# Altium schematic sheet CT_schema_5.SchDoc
size 251 x 159 mm
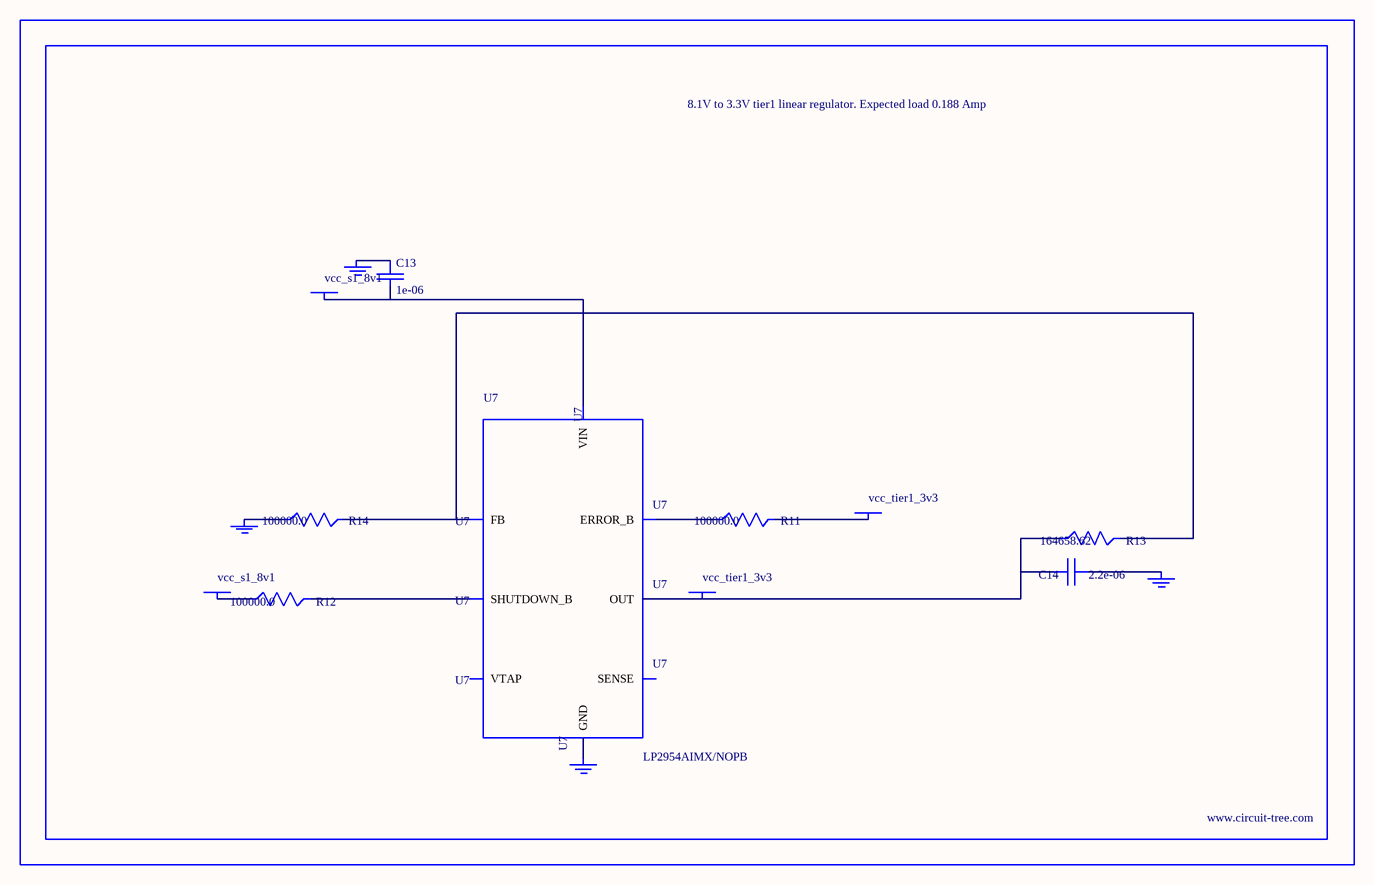
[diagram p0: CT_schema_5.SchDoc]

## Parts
BORDER4  (no value)
C13  1e-06  [EXV-9B]
C14  2.2e-06  [EXV-9B]
GND_INSTANCE_4_0  (no value)
GND_INSTANCE_4_1  (no value)
GND_INSTANCE_4_2  (no value)
GND_INSTANCE_4_3  (no value)
POWER_INSTANCE_4_0  vcc_s1_8v1
POWER_INSTANCE_4_1  vcc_tier1_3v3
POWER_INSTANCE_4_2  vcc_s1_8v1
POWER_INSTANCE_4_3  vcc_tier1_3v3
R11  100000.0  [R0603]
R12  100000.0  [R0603]
R13  164658.62  [R0603]
R14  100000.0  [R0603]
U7  LP2954AIMX/NOPB  [LP2954]

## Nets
NetC13_1: C13.1 GND_INSTANCE_4_2.0(GND)
NetC13_2: C13.2 POWER_INSTANCE_4_2.0(PWR) U7.8(VIN)
NetC14_1: C14.1 GND_INSTANCE_4_0.0(GND)
NetC14_2: C14.2 POWER_INSTANCE_4_3.0(PWR) R13.1 U7.1(OUT)
NetGND_INSTANCE_4_1_0: GND_INSTANCE_4_1.0(GND) R14.1
NetGND_INSTANCE_4_3_0: GND_INSTANCE_4_3.0(GND) U7.4(GND)
NetPOWER_INSTANCE_4_0_0: POWER_INSTANCE_4_0.0(PWR) R12.1
NetPOWER_INSTANCE_4_1_0: POWER_INSTANCE_4_1.0(PWR) R11.2
NetR11_1: R11.1 U7.5(ERROR_B)
NetR12_2: R12.2 U7.3(SHUTDOWN_B)
NetR13_2: R13.2 R14.2 U7.7(FB)

Not connected (* = marked no-connect by the designer): U7 2(SENSE) 6(VTAP)

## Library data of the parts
BORDER4 = BORDER_PAGE4
C13 = EDK105M050A9BAA
C14 = EDK225M050A9BAA
GND_INSTANCE_4_0-GND_INSTANCE_4_3 = GND
POWER_INSTANCE_4_0-POWER_INSTANCE_4_3 = PWR
R11 R12 R14 = RC0603JR-07100KL
R13 = R13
